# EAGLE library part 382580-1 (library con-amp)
SOCKET SIMM II CL DUAL READOUT Source: ENG_CD_382580_E.pdf
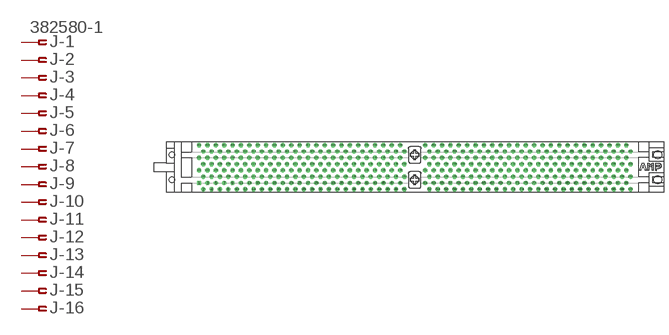
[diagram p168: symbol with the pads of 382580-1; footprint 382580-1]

Designator prefix J; gates -1=PIN-FV -2=PIN-F -3=PIN-F -4=PIN-F -5=PIN-F -6=PIN-F -7=PIN-F -8=PIN-F -9=PIN-F -10=PIN-F -11=PIN-F -12=PIN-F -13=PIN-F -14=PIN-F -15=PIN-F -16=PIN-F -17=PIN-F -18=PIN-F -19=PIN-F -20=PIN-F -21=PIN-F -22=PIN-F -23=PIN-F -24=PIN-F -25=PIN-F -26=PIN-F -27=PIN-F -28=PIN-F -29=PIN-F -30=PIN-F -31=PIN-F -32=PIN-F -33=PIN-F -34=PIN-F -35=PIN-F -36=PIN-F -37=PIN-F -38=PIN-F -39=PIN-F -40=PIN-F -41=PIN-F -42=PIN-F -43=PIN-F -44=PIN-F -45=PIN-F -46=PIN-F -47=PIN-F -48=PIN-F -49=PIN-F -50=PIN-F -51=PIN-F -52=PIN-F -53=PIN-F -54=PIN-F -55=PIN-F -56=PIN-F -57=PIN-F -58=PIN-F -59=PIN-F -60=PIN-F -61=PIN-F -62=PIN-F -63=PIN-F -64=PIN-F -65=PIN-F -66=PIN-F -67=PIN-F -68=PIN-F -69=PIN-F -70=PIN-F -71=PIN-F -72=PIN-F -73=PIN-F -74=PIN-F -75=PIN-F -76=PIN-F -77=PIN-F -78=PIN-F -79=PIN-F -80=PIN-F -81=PIN-F -82=PIN-F -83=PIN-F -84=PIN-F -85=PIN-F -86=PIN-F -87=PIN-F -88=PIN-F -89=PIN-F -90=PIN-F -91=PIN-F -92=PIN-F -93=PIN-F -94=PIN-F -95=PIN-F -96=PIN-F -97=PIN-F -98=PIN-F -99=PIN-F -100=PIN-F -101=PIN-F -102=PIN-F -103=PIN-F -104=PIN-F -105=PIN-F -106=PIN-F -107=PIN-F -108=PIN-F -109=PIN-F -110=PIN-F -111=PIN-F -112=PIN-F -113=PIN-F -114=PIN-F -115=PIN-F -116=PIN-F -117=PIN-F -118=PIN-F -119=PIN-F -120=PIN-F -121=PIN-F -122=PIN-F -123=PIN-F -124=PIN-F -125=PIN-F -126=PIN-F -127=PIN-F -128=PIN-F -129=PIN-F -130=PIN-F -131=PIN-F -132=PIN-F -133=PIN-F -134=PIN-F -135=PIN-F -136=PIN-F -137=PIN-F -138=PIN-F -139=PIN-F -140=PIN-F -141=PIN-F -142=PIN-F -143=PIN-F -144=PIN-F -145=PIN-F -146=PIN-F -147=PIN-F -148=PIN-F -149=PIN-F -150=PIN-F -151=PIN-F -152=PIN-F -153=PIN-F -154=PIN-F -155=PIN-F -156=PIN-F -157=PIN-F -158=PIN-F -159=PIN-F -160=PIN-F -161=PIN-F -162=PIN-F -163=PIN-F -164=PIN-F -165=PIN-F -166=PIN-F -167=PIN-F -168=PIN-F -169=PIN-F -170=PIN-F -171=PIN-F -172=PIN-F -173=PIN-F -174=PIN-F -175=PIN-F -176=PIN-F -177=PIN-F -178=PIN-F -179=PIN-F -180=PIN-F -181=PIN-F -182=PIN-F -183=PIN-F -184=PIN-F -185=PIN-F -186=PIN-F -187=PIN-F -188=PIN-F -189=PIN-F -190=PIN-F -191=PIN-F -192=PIN-F -193=PIN-F -194=PIN-F -195=PIN-F -196=PIN-F -197=PIN-F -198=PIN-F -199=PIN-F -200=PIN-F -201=PIN-F -202=PIN-F -203=PIN-F -204=PIN-F -205=PIN-F -206=PIN-F -207=PIN-F -208=PIN-F -209=PIN-F -210=PIN-F -211=PIN-F -212=PIN-F -213=PIN-F -214=PIN-F -215=PIN-F -216=PIN-F -217=PIN-F -218=PIN-F -219=PIN-F -220=PIN-F -221=PIN-F -222=PIN-F -223=PIN-F -224=PIN-F -225=PIN-F -226=PIN-F -227=PIN-F -228=PIN-F -229=PIN-F -230=PIN-F -231=PIN-F -232=PIN-F -233=PIN-F -234=PIN-F -235=PIN-F -236=PIN-F -237=PIN-F -238=PIN-F -239=PIN-F -240=PIN-F -241=PIN-F -242=PIN-F -243=PIN-F -244=PIN-F -245=PIN-F -246=PIN-F -247=PIN-F -248=PIN-F -249=PIN-F -250=PIN-F -251=PIN-F -252=PIN-F -253=PIN-F -254=PIN-F -255=PIN-F -256=PIN-F -257=PIN-F -258=PIN-F -259=PIN-F -260=PIN-F -261=PIN-F -262=PIN-F -263=PIN-F -264=PIN-F -265=PIN-F -266=PIN-F -267=PIN-F -268=PIN-F -269=PIN-F -270=PIN-F -271=PIN-F -272=PIN-F -273=PIN-F -274=PIN-F -275=PIN-F -276=PIN-F -277=PIN-F -278=PIN-F -279=PIN-F -280=PIN-F -281=PIN-F -282=PIN-F -283=PIN-F -284=PIN-F -285=PIN-F -286=PIN-F -287=PIN-F -288=PIN-F -289=PIN-F -290=PIN-F -291=PIN-F -292=PIN-F -293=PIN-F -294=PIN-F -295=PIN-F -296=PIN-F -297=PIN-F -298=PIN-F -299=PIN-F -300=PIN-F -301=PIN-F -302=PIN-F -303=PIN-F -304=PIN-F -305=PIN-F -306=PIN-F -307=PIN-F -308=PIN-F -309=PIN-F -310=PIN-F -311=PIN-F -312=PIN-F -313=PIN-F -314=PIN-F -315=PIN-F -316=PIN-F -317=PIN-F -318=PIN-F -319=PIN-F -320=PIN-F -321=PIN-F -322=PIN-F -323=PIN-F -324=PIN-F -325=PIN-F -326=PIN-F -327=PIN-F -328=PIN-F -329=PIN-F -330=PIN-F -331=PIN-F -332=PIN-F -333=PIN-F -334=PIN-F -335=PIN-F -336=PIN-F -337=PIN-F -338=PIN-F -339=PIN-F -340=PIN-F -341=PIN-F -342=PIN-F -343=PIN-F -344=PIN-F -345=PIN-F -346=PIN-F -347=PIN-F -348=PIN-F -349=PIN-F -350=PIN-F -351=PIN-F -352=PIN-F -353=PIN-F -354=PIN-F -355=PIN-F -356=PIN-F -357=PIN-F -358=PIN-F -359=PIN-F -360=PIN-F -361=PIN-F -362=PIN-F -363=PIN-F -364=PIN-F -365=PIN-F -366=PIN-F -367=PIN-F -368=PIN-F -369=PIN-F -370=PIN-F -371=PIN-F -372=PIN-F -373=PIN-F -374=PIN-F -375=PIN-F -376=PIN-F -377=PIN-F -378=PIN-F -379=PIN-F -380=PIN-F -381=PIN-F -382=PIN-F -383=PIN-F -384=PIN-F -385=PIN-F -386=PIN-F -387=PIN-F -388=PIN-F -389=PIN-F -390=PIN-F -391=PIN-F -392=PIN-F -393=PIN-F -394=PIN-F -395=PIN-F -396=PIN-F -397=PIN-F -398=PIN-F -399=PIN-F -400=PIN-F

## 382580-1 (OC_FARNELL: unknown; OC_NEWARK: unknown)  [382580-1]
1  -1:1  pas
2  -2:1  pas
3  -3:1  pas
4  -4:1  pas
5  -5:1  pas
6  -6:1  pas
7  -7:1  pas
8  -8:1  pas
9  -9:1  pas
10  -10:1  pas
11  -11:1  pas
12  -12:1  pas
13  -13:1  pas
14  -14:1  pas
15  -15:1  pas
16  -16:1  pas
17  -17:1  pas
18  -18:1  pas
19  -19:1  pas
20  -20:1  pas
21  -21:1  pas
22  -22:1  pas
23  -23:1  pas
24  -24:1  pas
25  -25:1  pas
26  -26:1  pas
27  -27:1  pas
28  -28:1  pas
29  -29:1  pas
30  -30:1  pas
31  -31:1  pas
32  -32:1  pas
33  -33:1  pas
34  -34:1  pas
35  -35:1  pas
36  -36:1  pas
37  -37:1  pas
38  -38:1  pas
39  -39:1  pas
40  -40:1  pas
41  -41:1  pas
42  -42:1  pas
43  -43:1  pas
44  -44:1  pas
45  -45:1  pas
46  -46:1  pas
47  -47:1  pas
48  -48:1  pas
49  -49:1  pas
50  -50:1  pas
51  -51:1  pas
52  -52:1  pas
53  -53:1  pas
54  -54:1  pas
55  -55:1  pas
56  -56:1  pas
57  -57:1  pas
58  -58:1  pas
59  -59:1  pas
60  -60:1  pas
61  -61:1  pas
62  -62:1  pas
63  -63:1  pas
64  -64:1  pas
65  -65:1  pas
66  -66:1  pas
67  -67:1  pas
68  -68:1  pas
69  -69:1  pas
70  -70:1  pas
71  -71:1  pas
72  -72:1  pas
73  -73:1  pas
74  -74:1  pas
75  -75:1  pas
76  -76:1  pas
77  -77:1  pas
78  -78:1  pas
79  -79:1  pas
80  -80:1  pas
81  -81:1  pas
82  -82:1  pas
83  -83:1  pas
84  -84:1  pas
85  -85:1  pas
86  -86:1  pas
87  -87:1  pas
88  -88:1  pas
89  -89:1  pas
90  -90:1  pas
91  -91:1  pas
92  -92:1  pas
93  -93:1  pas
94  -94:1  pas
95  -95:1  pas
96  -96:1  pas
97  -97:1  pas
98  -98:1  pas
99  -99:1  pas
100  -100:1  pas
101  -101:1  pas
102  -102:1  pas
103  -103:1  pas
104  -104:1  pas
105  -105:1  pas
106  -106:1  pas
107  -107:1  pas
108  -108:1  pas
109  -109:1  pas
110  -110:1  pas
111  -111:1  pas
112  -112:1  pas
113  -113:1  pas
114  -114:1  pas
115  -115:1  pas
116  -116:1  pas
117  -117:1  pas
118  -118:1  pas
119  -119:1  pas
120  -120:1  pas
121  -121:1  pas
122  -122:1  pas
123  -123:1  pas
124  -124:1  pas
125  -125:1  pas
126  -126:1  pas
127  -127:1  pas
128  -128:1  pas
129  -129:1  pas
130  -130:1  pas
131  -131:1  pas
132  -132:1  pas
133  -133:1  pas
134  -134:1  pas
135  -135:1  pas
136  -136:1  pas
137  -137:1  pas
138  -138:1  pas
139  -139:1  pas
140  -140:1  pas
141  -141:1  pas
142  -142:1  pas
143  -143:1  pas
144  -144:1  pas
145  -145:1  pas
146  -146:1  pas
147  -147:1  pas
148  -148:1  pas
149  -149:1  pas
150  -150:1  pas
151  -151:1  pas
152  -152:1  pas
153  -153:1  pas
154  -154:1  pas
155  -155:1  pas
156  -156:1  pas
157  -157:1  pas
158  -158:1  pas
159  -159:1  pas
160  -160:1  pas
161  -161:1  pas
162  -162:1  pas
163  -163:1  pas
164  -164:1  pas
165  -165:1  pas
166  -166:1  pas
167  -167:1  pas
168  -168:1  pas
169  -169:1  pas
170  -170:1  pas
171  -171:1  pas
172  -172:1  pas
173  -173:1  pas
174  -174:1  pas
175  -175:1  pas
176  -176:1  pas
177  -177:1  pas
178  -178:1  pas
179  -179:1  pas
180  -180:1  pas
181  -181:1  pas
182  -182:1  pas
183  -183:1  pas
184  -184:1  pas
185  -185:1  pas
186  -186:1  pas
187  -187:1  pas
188  -188:1  pas
189  -189:1  pas
190  -190:1  pas
191  -191:1  pas
192  -192:1  pas
193  -193:1  pas
194  -194:1  pas
195  -195:1  pas
196  -196:1  pas
197  -197:1  pas
198  -198:1  pas
199  -199:1  pas
200  -200:1  pas
201  -201:1  pas
202  -202:1  pas
203  -203:1  pas
204  -204:1  pas
205  -205:1  pas
206  -206:1  pas
207  -207:1  pas
208  -208:1  pas
209  -209:1  pas
210  -210:1  pas
211  -211:1  pas
212  -212:1  pas
213  -213:1  pas
214  -214:1  pas
215  -215:1  pas
216  -216:1  pas
217  -217:1  pas
218  -218:1  pas
219  -219:1  pas
220  -220:1  pas
221  -221:1  pas
222  -222:1  pas
223  -223:1  pas
224  -224:1  pas
225  -225:1  pas
226  -226:1  pas
227  -227:1  pas
228  -228:1  pas
229  -229:1  pas
230  -230:1  pas
231  -231:1  pas
232  -232:1  pas
233  -233:1  pas
234  -234:1  pas
235  -235:1  pas
236  -236:1  pas
237  -237:1  pas
238  -238:1  pas
239  -239:1  pas
240  -240:1  pas
241  -241:1  pas
242  -242:1  pas
243  -243:1  pas
244  -244:1  pas
245  -245:1  pas
246  -246:1  pas
247  -247:1  pas
248  -248:1  pas
249  -249:1  pas
250  -250:1  pas
251  -251:1  pas
252  -252:1  pas
253  -253:1  pas
254  -254:1  pas
255  -255:1  pas
256  -256:1  pas
257  -257:1  pas
258  -258:1  pas
259  -259:1  pas
260  -260:1  pas
261  -261:1  pas
262  -262:1  pas
263  -263:1  pas
264  -264:1  pas
265  -265:1  pas
266  -266:1  pas
267  -267:1  pas
268  -268:1  pas
269  -269:1  pas
270  -270:1  pas
271  -271:1  pas
272  -272:1  pas
273  -273:1  pas
274  -274:1  pas
275  -275:1  pas
276  -276:1  pas
277  -277:1  pas
278  -278:1  pas
279  -279:1  pas
280  -280:1  pas
281  -281:1  pas
282  -282:1  pas
283  -283:1  pas
284  -284:1  pas
285  -285:1  pas
286  -286:1  pas
287  -287:1  pas
288  -288:1  pas
289  -289:1  pas
290  -290:1  pas
291  -291:1  pas
292  -292:1  pas
293  -293:1  pas
294  -294:1  pas
295  -295:1  pas
296  -296:1  pas
297  -297:1  pas
298  -298:1  pas
299  -299:1  pas
300  -300:1  pas
301  -301:1  pas
302  -302:1  pas
303  -303:1  pas
304  -304:1  pas
305  -305:1  pas
306  -306:1  pas
307  -307:1  pas
308  -308:1  pas
309  -309:1  pas
310  -310:1  pas
311  -311:1  pas
312  -312:1  pas
313  -313:1  pas
314  -314:1  pas
315  -315:1  pas
316  -316:1  pas
317  -317:1  pas
318  -318:1  pas
319  -319:1  pas
320  -320:1  pas
321  -321:1  pas
322  -322:1  pas
323  -323:1  pas
324  -324:1  pas
325  -325:1  pas
326  -326:1  pas
327  -327:1  pas
328  -328:1  pas
329  -329:1  pas
330  -330:1  pas
331  -331:1  pas
332  -332:1  pas
333  -333:1  pas
334  -334:1  pas
335  -335:1  pas
336  -336:1  pas
337  -337:1  pas
338  -338:1  pas
339  -339:1  pas
340  -340:1  pas
341  -341:1  pas
342  -342:1  pas
343  -343:1  pas
344  -344:1  pas
345  -345:1  pas
346  -346:1  pas
347  -347:1  pas
348  -348:1  pas
349  -349:1  pas
350  -350:1  pas
351  -351:1  pas
352  -352:1  pas
353  -353:1  pas
354  -354:1  pas
355  -355:1  pas
356  -356:1  pas
357  -357:1  pas
358  -358:1  pas
359  -359:1  pas
360  -360:1  pas
361  -361:1  pas
362  -362:1  pas
363  -363:1  pas
364  -364:1  pas
365  -365:1  pas
366  -366:1  pas
367  -367:1  pas
368  -368:1  pas
369  -369:1  pas
370  -370:1  pas
371  -371:1  pas
372  -372:1  pas
373  -373:1  pas
374  -374:1  pas
375  -375:1  pas
376  -376:1  pas
377  -377:1  pas
378  -378:1  pas
379  -379:1  pas
380  -380:1  pas
381  -381:1  pas
382  -382:1  pas
383  -383:1  pas
384  -384:1  pas
385  -385:1  pas
386  -386:1  pas
387  -387:1  pas
388  -388:1  pas
389  -389:1  pas
390  -390:1  pas
391  -391:1  pas
392  -392:1  pas
393  -393:1  pas
394  -394:1  pas
395  -395:1  pas
396  -396:1  pas
397  -397:1  pas
398  -398:1  pas
399  -399:1  pas
400  -400:1  pas

## Footprint 382580-1 (pad centres in mm)
DIMM I Dual Read Out
drill 0.813 square: 1 -65.405,-4.763
drill 0.813 octagon: 2 -64.135,-6.668; 3 -62.865,-4.763; 4 -61.595,-6.668; 5 -60.325,-4.763; 6 -59.055,-6.668; 7 -57.785,-4.763; 8 -56.515,-6.668; 9 -55.245,-4.763; 10 -53.975,-6.668; 11 -52.705,-4.763; 12 -51.435,-6.668; 13 -50.165,-4.763; 14 -48.895,-6.668; 15 -47.625,-4.763; 16 -46.355,-6.668; 17 -45.085,-4.763; 18 -43.815,-6.668; 19 -42.545,-4.763; 20 -41.275,-6.668; 21 -40.005,-4.763; 22 -38.735,-6.668; 23 -37.465,-4.763; 24 -36.195,-6.668; 25 -34.925,-4.763; 26 -33.655,-6.668; 27 -32.385,-4.763; 28 -31.115,-6.668; 29 -29.845,-4.763; 30 -28.575,-6.668; 31 -27.305,-4.763; 32 -26.035,-6.668; 33 -24.765,-4.763; 34 -23.495,-6.668; 35 -22.225,-4.763; 36 -20.955,-6.668; 37 -19.685,-4.763; 38 -18.415,-6.668; 39 -17.145,-4.763; 40 -15.875,-6.668; 41 -14.605,-4.763; 42 -13.335,-6.668; 43 -12.065,-4.763; 44 -10.795,-6.668; 45 -9.525,-4.763; 46 -8.255,-6.668; 47 -6.985,-4.763; 48 -5.715,-6.668; 49 -4.445,-4.763; 50 -3.175,-6.668; 51 3.175,-4.763; 52 4.445,-6.668; 53 5.715,-4.763; 54 6.985,-6.668; 55 8.255,-4.763; 56 9.525,-6.668; 57 10.795,-4.763; 58 12.065,-6.668; 59 13.335,-4.763; 60 14.605,-6.668; 61 15.875,-4.763; 62 17.145,-6.668; 63 18.415,-4.763; 64 19.685,-6.668; 65 20.955,-4.763; 66 22.225,-6.668; 67 23.495,-4.763; 68 24.765,-6.668; 69 26.035,-4.763; 70 27.305,-6.668; 71 28.575,-4.763; 72 29.845,-6.668; 73 31.115,-4.763; 74 32.385,-6.668; 75 33.655,-4.763; 76 34.925,-6.668; 77 36.195,-4.763; 78 37.465,-6.668; 79 38.735,-4.763; 80 40.005,-6.668; 81 41.275,-4.763; 82 42.545,-6.668; 83 43.815,-4.763; 84 45.085,-6.668; 85 46.355,-4.763; 86 47.625,-6.668; 87 48.895,-4.763; 88 50.165,-6.668; 89 51.435,-4.763; 90 52.705,-6.668; 91 53.975,-4.763; 92 55.245,-6.668; 93 56.515,-4.763; 94 57.785,-6.668; 95 59.055,-4.763; 96 60.325,-6.668; 97 61.595,-4.763; 98 62.865,-6.668; 99 64.135,-4.763; 100 65.405,-6.668; 101 -65.405,-0.953; 102 -64.135,-2.857; 103 -62.865,-0.953; 104 -61.595,-2.857; 105 -60.325,-0.953; 106 -59.055,-2.857; 107 -57.785,-0.953; 108 -56.515,-2.857; 109 -55.245,-0.953; 110 -53.975,-2.857; 111 -52.705,-0.953; 112 -51.435,-2.857; 113 -50.165,-0.953; 114 -48.895,-2.857; 115 -47.625,-0.953; 116 -46.355,-2.857; 117 -45.085,-0.953; 118 -43.815,-2.857; 119 -42.545,-0.953; 120 -41.275,-2.857; 121 -40.005,-0.953; 122 -38.735,-2.857; 123 -37.465,-0.953; 124 -36.195,-2.857; 125 -34.925,-0.953; 126 -33.655,-2.857; 127 -32.385,-0.953; 128 -31.115,-2.857; 129 -29.845,-0.953; 130 -28.575,-2.857; 131 -27.305,-0.953; 132 -26.035,-2.857; 133 -24.765,-0.953; 134 -23.495,-2.857; 135 -22.225,-0.953; 136 -20.955,-2.857; 137 -19.685,-0.953; 138 -18.415,-2.857; 139 -17.145,-0.953; 140 -15.875,-2.857; 141 -14.605,-0.953; 142 -13.335,-2.857; 143 -12.065,-0.953; 144 -10.795,-2.857; 145 -9.525,-0.953; 146 -8.255,-2.857; 147 -6.985,-0.953; 148 -5.715,-2.857; 149 -4.445,-0.953; 150 -3.175,-2.857; 151 3.175,-0.953; 152 4.445,-2.857; 153 5.715,-0.953; 154 6.985,-2.857; 155 8.255,-0.953; 156 9.525,-2.857; 157 10.795,-0.953; 158 12.065,-2.857; 159 13.335,-0.953; 160 14.605,-2.857; 161 15.875,-0.953; 162 17.145,-2.857; 163 18.415,-0.953; 164 19.685,-2.857; 165 20.955,-0.953; 166 22.225,-2.857; 167 23.495,-0.953; 168 24.765,-2.857; 169 26.035,-0.953; 170 27.305,-2.857; 171 28.575,-0.953; 172 29.845,-2.857; 173 31.115,-0.953; 174 32.385,-2.857; 175 33.655,-0.953; 176 34.925,-2.857; 177 36.195,-0.953; 178 37.465,-2.857; 179 38.735,-0.953; 180 40.005,-2.857; 181 41.275,-0.953; 182 42.545,-2.857; 183 43.815,-0.953; 184 45.085,-2.857; 185 46.355,-0.953; 186 47.625,-2.857; 187 48.895,-0.953; 188 50.165,-2.857; 189 51.435,-0.953; 190 52.705,-2.857; 191 53.975,-0.953; 192 55.245,-2.857; 193 56.515,-0.953; 194 57.785,-2.857; 195 59.055,-0.953; 196 60.325,-2.857; 197 61.595,-0.953; 198 62.865,-2.857; 199 64.135,-0.953; 200 65.405,-2.857; 201 -65.405,2.857; 202 -64.135,0.953; 203 -62.865,2.857; 204 -61.595,0.953; 205 -60.325,2.857; 206 -59.055,0.953; 207 -57.785,2.857; 208 -56.515,0.953; 209 -55.245,2.857; 210 -53.975,0.953; 211 -52.705,2.857; 212 -51.435,0.953; 213 -50.165,2.857; 214 -48.895,0.953; 215 -47.625,2.857; 216 -46.355,0.953; 217 -45.085,2.857; 218 -43.815,0.953; 219 -42.545,2.857; 220 -41.275,0.953; 221 -40.005,2.857; 222 -38.735,0.953; 223 -37.465,2.857; 224 -36.195,0.953; 225 -34.925,2.857; 226 -33.655,0.953; 227 -32.385,2.857; 228 -31.115,0.953; 229 -29.845,2.857; 230 -28.575,0.953; 231 -27.305,2.857; 232 -26.035,0.953; 233 -24.765,2.857; 234 -23.495,0.953; 235 -22.225,2.857; 236 -20.955,0.953; 237 -19.685,2.857; 238 -18.415,0.953; 239 -17.145,2.857; 240 -15.875,0.953; 241 -14.605,2.857; 242 -13.335,0.953; 243 -12.065,2.857; 244 -10.795,0.953; 245 -9.525,2.857; 246 -8.255,0.953; 247 -6.985,2.857; 248 -5.715,0.953; 249 -4.445,2.857; 250 -3.175,0.953; 251 3.175,2.857; 252 4.445,0.953; 253 5.715,2.857; 254 6.985,0.953; 255 8.255,2.857; 256 9.525,0.953; 257 10.795,2.857; 258 12.065,0.953; 259 13.335,2.857; 260 14.605,0.953; 261 15.875,2.857; 262 17.145,0.953; 263 18.415,2.857; 264 19.685,0.953; 265 20.955,2.857; 266 22.225,0.953; 267 23.495,2.857; 268 24.765,0.953; 269 26.035,2.857; 270 27.305,0.953; 271 28.575,2.857; 272 29.845,0.953; 273 31.115,2.857; 274 32.385,0.953; 275 33.655,2.857; 276 34.925,0.953; 277 36.195,2.857; 278 37.465,0.953; 279 38.735,2.857; 280 40.005,0.953; 281 41.275,2.857; 282 42.545,0.953; 283 43.815,2.857; 284 45.085,0.953; 285 46.355,2.857; 286 47.625,0.953; 287 48.895,2.857; 288 50.165,0.953; 289 51.435,2.857; 290 52.705,0.953; 291 53.975,2.857; 292 55.245,0.953; 293 56.515,2.857; 294 57.785,0.953; 295 59.055,2.857; 296 60.325,0.953; 297 61.595,2.857; 298 62.865,0.953; 299 64.135,2.857; 300 65.405,0.953; 301 -65.405,6.668; 302 -64.135,4.763; 303 -62.865,6.668; 304 -61.595,4.763; 305 -60.325,6.668; 306 -59.055,4.763; 307 -57.785,6.668; 308 -56.515,4.763; 309 -55.245,6.668; 310 -53.975,4.763; 311 -52.705,6.668; 312 -51.435,4.763; 313 -50.165,6.668; 314 -48.895,4.763; 315 -47.625,6.668; 316 -46.355,4.763; 317 -45.085,6.668; 318 -43.815,4.763; 319 -42.545,6.668; 320 -41.275,4.763; 321 -40.005,6.668; 322 -38.735,4.763; 323 -37.465,6.668; 324 -36.195,4.763; 325 -34.925,6.668; 326 -33.655,4.763; 327 -32.385,6.668; 328 -31.115,4.763; 329 -29.845,6.668; 330 -28.575,4.763; 331 -27.305,6.668; 332 -26.035,4.763; 333 -24.765,6.668; 334 -23.495,4.763; 335 -22.225,6.668; 336 -20.955,4.763; 337 -19.685,6.668; 338 -18.415,4.763; 339 -17.145,6.668; 340 -15.875,4.763; 341 -14.605,6.668; 342 -13.335,4.763; 343 -12.065,6.668; 344 -10.795,4.763; 345 -9.525,6.668; 346 -8.255,4.763; 347 -6.985,6.668; 348 -5.715,4.763; 349 -4.445,6.668; 350 -3.175,4.763; 351 3.175,6.668; 352 4.445,4.763; 353 5.715,6.668; 354 6.985,4.763; 355 8.255,6.668; 356 9.525,4.763; 357 10.795,6.668; 358 12.065,4.763; 359 13.335,6.668; 360 14.605,4.763; 361 15.875,6.668; 362 17.145,4.763; 363 18.415,6.668; 364 19.685,4.763; 365 20.955,6.668; 366 22.225,4.763; 367 23.495,6.668; 368 24.765,4.763; 369 26.035,6.668; 370 27.305,4.763; 371 28.575,6.668; 372 29.845,4.763; 373 31.115,6.668; 374 32.385,4.763; 375 33.655,6.668; 376 34.925,4.763; 377 36.195,6.668; 378 37.465,4.763; 379 38.735,6.668; 380 40.005,4.763; 381 41.275,6.668; 382 42.545,4.763; 383 43.815,6.668; 384 45.085,4.763; 385 46.355,6.668; 386 47.625,4.763; 387 48.895,6.668; 388 50.165,4.763; 389 51.435,6.668; 390 52.705,4.763; 391 53.975,6.668; 392 55.245,4.763; 393 56.515,6.668; 394 57.785,4.763; 395 59.055,6.668; 396 60.325,4.763; 397 61.595,6.668; 398 62.865,4.763; 399 64.135,6.668; 400 65.405,4.763
hole 1.575 at -73.66,-3.81
hole 2.362 at 0,-3.81
hole 2.362 at 73.66,-3.81
hole 1.575 at -73.66,3.81
hole 2.362 at 0,3.81
hole 2.362 at 73.66,3.81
